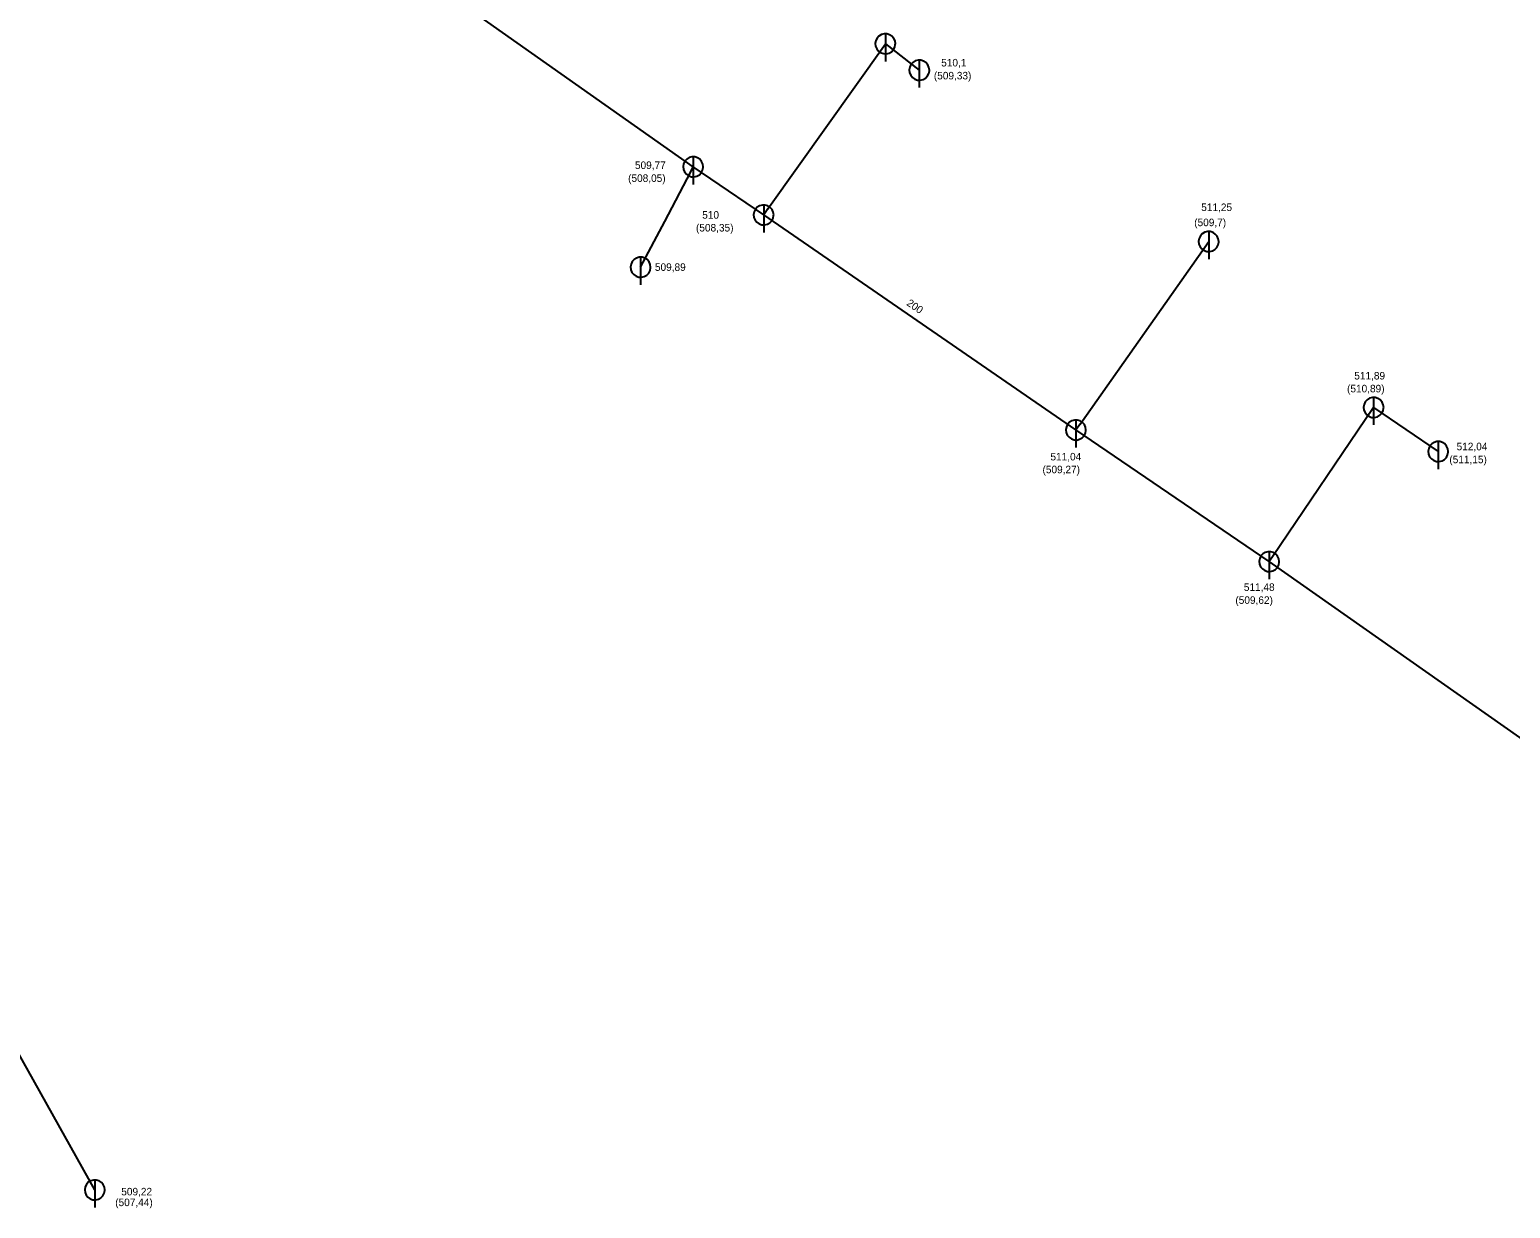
# Model space of a CAD drawing. Extents: x -476058 to -471893, y -1155786 to -1152000.
# Drawn here: x -475206.1 to -475058.6, y -1154421.6 to -1154304.2 of the extents above; entities that cross this region are included whole.
import ezdxf

# ---------------------------------------------------------------- set-up
doc = ezdxf.new("R2010")
doc.units = 0
for name, color, linetype in [('Vrstva 10', 7, 'Continuous'), ('Vrstva 18', 7, 'Continuous'), ('Vrstva 3', 7, 'Continuous'), ('Vrstva 4', 7, 'Continuous'), ('Vrstva 45', 7, 'Continuous'), ('Vrstva 50', 7, 'Continuous'), ('Vrstva 51', 7, 'Continuous')]:
    doc.layers.add(name, color=color, linetype=linetype)

msp = doc.modelspace()

# ---------------------------------------------------------------- linework, layer by layer
at = {"layer": 'Vrstva 10'}
for p, q in [((-475120.87, -1154304.59), (-475120.87, -1154307.34)), ((-475117.49, -1154307.21), (-475117.49, -1154309.96)), ((-475140.01, -1154316.85), (-475140.01, -1154319.6)), ((-475132.99, -1154321.64), (-475132.99, -1154324.39)), ((-475088.67, -1154324.29), (-475088.67, -1154327.04)), ((-475145.25, -1154326.84), (-475145.25, -1154329.59)), ((-475072.24, -1154340.81), (-475072.24, -1154343.56)), ((-475101.89, -1154343.06), (-475101.89, -1154345.81)), ((-475065.81, -1154345.2), (-475065.81, -1154347.95)), ((-475082.64, -1154356.17), (-475082.64, -1154358.92)), ((-475199.61, -1154418.76), (-475199.61, -1154421.51))]:
    msp.add_line(p, q, dxfattribs=at)
for points in [[(-475119.87, -1154305.59), (-475119.91, -1154305.31), (-475120.03, -1154305.05), (-475120.21, -1154304.84), (-475120.45, -1154304.69), (-475120.72, -1154304.6), (-475121, -1154304.6), (-475121.27, -1154304.67), (-475121.51, -1154304.82), (-475121.7, -1154305.03), (-475121.83, -1154305.28), (-475121.87, -1154305.56), (-475121.84, -1154305.84), (-475121.73, -1154306.1), (-475121.55, -1154306.32), (-475121.32, -1154306.48), (-475121.06, -1154306.57), (-475120.77, -1154306.59), (-475120.5, -1154306.52), (-475120.26, -1154306.38), (-475120.06, -1154306.17), (-475119.93, -1154305.92), (-475119.88, -1154305.65), (-475119.87, -1154305.59)], [(-475116.49, -1154308.21), (-475116.53, -1154307.94), (-475116.64, -1154307.68), (-475116.83, -1154307.46), (-475117.06, -1154307.31), (-475117.33, -1154307.23), (-475117.61, -1154307.22), (-475117.89, -1154307.3), (-475118.13, -1154307.45), (-475118.32, -1154307.65), (-475118.44, -1154307.91), (-475118.49, -1154308.19), (-475118.46, -1154308.47), (-475118.35, -1154308.73), (-475118.17, -1154308.95), (-475117.94, -1154309.11), (-475117.67, -1154309.2), (-475117.39, -1154309.21), (-475117.11, -1154309.14), (-475116.87, -1154309), (-475116.67, -1154308.8), (-475116.54, -1154308.55), (-475116.49, -1154308.27), (-475116.49, -1154308.21)], [(-475139.01, -1154317.85), (-475139.05, -1154317.57), (-475139.17, -1154317.31), (-475139.35, -1154317.1), (-475139.59, -1154316.95), (-475139.85, -1154316.86), (-475140.14, -1154316.86), (-475140.41, -1154316.93), (-475140.65, -1154317.08), (-475140.84, -1154317.29), (-475140.96, -1154317.54), (-475141.01, -1154317.82), (-475140.98, -1154318.1), (-475140.87, -1154318.36), (-475140.69, -1154318.58), (-475140.46, -1154318.74), (-475140.19, -1154318.83), (-475139.91, -1154318.85), (-475139.64, -1154318.78), (-475139.39, -1154318.64), (-475139.2, -1154318.43), (-475139.07, -1154318.18), (-475139.01, -1154317.91), (-475139.01, -1154317.85)], [(-475131.99, -1154322.64), (-475132.03, -1154322.36), (-475132.15, -1154322.1), (-475132.33, -1154321.89), (-475132.57, -1154321.74), (-475132.84, -1154321.65), (-475133.12, -1154321.65), (-475133.39, -1154321.72), (-475133.63, -1154321.87), (-475133.82, -1154322.08), (-475133.95, -1154322.33), (-475133.99, -1154322.61), (-475133.96, -1154322.89), (-475133.85, -1154323.15), (-475133.68, -1154323.37), (-475133.45, -1154323.53), (-475133.18, -1154323.62), (-475132.9, -1154323.64), (-475132.62, -1154323.57), (-475132.38, -1154323.43), (-475132.18, -1154323.22), (-475132.05, -1154322.97), (-475132, -1154322.7), (-475131.99, -1154322.64)], [(-475087.67, -1154325.29), (-475087.71, -1154325.01), (-475087.82, -1154324.75), (-475088.01, -1154324.54), (-475088.24, -1154324.39), (-475088.51, -1154324.3), (-475088.79, -1154324.3), (-475089.07, -1154324.37), (-475089.31, -1154324.52), (-475089.5, -1154324.73), (-475089.62, -1154324.98), (-475089.67, -1154325.26), (-475089.64, -1154325.54), (-475089.53, -1154325.8), (-475089.35, -1154326.02), (-475089.12, -1154326.18), (-475088.85, -1154326.27), (-475088.57, -1154326.29), (-475088.29, -1154326.22), (-475088.05, -1154326.08), (-475087.85, -1154325.87), (-475087.73, -1154325.62), (-475087.67, -1154325.35), (-475087.67, -1154325.29)], [(-475144.25, -1154327.84), (-475144.29, -1154327.57), (-475144.41, -1154327.31), (-475144.59, -1154327.09), (-475144.83, -1154326.94), (-475145.1, -1154326.86), (-475145.38, -1154326.85), (-475145.65, -1154326.93), (-475145.89, -1154327.08), (-475146.08, -1154327.28), (-475146.2, -1154327.54), (-475146.25, -1154327.82), (-475146.22, -1154328.1), (-475146.11, -1154328.36), (-475145.93, -1154328.58), (-475145.7, -1154328.74), (-475145.43, -1154328.83), (-475145.15, -1154328.84), (-475144.88, -1154328.77), (-475144.63, -1154328.63), (-475144.44, -1154328.43), (-475144.31, -1154328.18), (-475144.25, -1154327.9), (-475144.25, -1154327.84)], [(-475071.24, -1154341.81), (-475071.28, -1154341.54), (-475071.4, -1154341.28), (-475071.58, -1154341.06), (-475071.82, -1154340.91), (-475072.09, -1154340.83), (-475072.37, -1154340.82), (-475072.64, -1154340.9), (-475072.88, -1154341.05), (-475073.07, -1154341.26), (-475073.2, -1154341.51), (-475073.24, -1154341.79), (-475073.21, -1154342.07), (-475073.1, -1154342.33), (-475072.93, -1154342.55), (-475072.7, -1154342.71), (-475072.43, -1154342.8), (-475072.15, -1154342.81), (-475071.87, -1154342.74), (-475071.63, -1154342.6), (-475071.43, -1154342.4), (-475071.3, -1154342.15), (-475071.25, -1154341.87), (-475071.24, -1154341.81)], [(-475100.89, -1154344.06), (-475100.93, -1154343.78), (-475101.05, -1154343.52), (-475101.23, -1154343.31), (-475101.47, -1154343.16), (-475101.73, -1154343.07), (-475102.02, -1154343.07), (-475102.29, -1154343.14), (-475102.53, -1154343.29), (-475102.72, -1154343.5), (-475102.84, -1154343.75), (-475102.89, -1154344.03), (-475102.86, -1154344.31), (-475102.75, -1154344.57), (-475102.57, -1154344.79), (-475102.34, -1154344.95), (-475102.07, -1154345.04), (-475101.79, -1154345.06), (-475101.52, -1154344.99), (-475101.27, -1154344.85), (-475101.08, -1154344.64), (-475100.95, -1154344.39), (-475100.89, -1154344.12), (-475100.89, -1154344.06)], [(-475064.81, -1154346.2), (-475064.85, -1154345.93), (-475064.97, -1154345.67), (-475065.15, -1154345.45), (-475065.38, -1154345.3), (-475065.65, -1154345.22), (-475065.94, -1154345.21), (-475066.21, -1154345.29), (-475066.45, -1154345.44), (-475066.64, -1154345.64), (-475066.76, -1154345.9), (-475066.81, -1154346.18), (-475066.78, -1154346.46), (-475066.67, -1154346.72), (-475066.49, -1154346.94), (-475066.26, -1154347.1), (-475065.99, -1154347.19), (-475065.71, -1154347.2), (-475065.43, -1154347.13), (-475065.19, -1154346.99), (-475065, -1154346.79), (-475064.87, -1154346.54), (-475064.81, -1154346.26), (-475064.81, -1154346.2)], [(-475081.64, -1154357.17), (-475081.68, -1154356.89), (-475081.8, -1154356.63), (-475081.98, -1154356.42), (-475082.22, -1154356.27), (-475082.48, -1154356.18), (-475082.77, -1154356.18), (-475083.04, -1154356.25), (-475083.28, -1154356.4), (-475083.47, -1154356.61), (-475083.59, -1154356.86), (-475083.64, -1154357.14), (-475083.61, -1154357.42), (-475083.5, -1154357.68), (-475083.32, -1154357.9), (-475083.09, -1154358.06), (-475082.82, -1154358.15), (-475082.54, -1154358.17), (-475082.27, -1154358.1), (-475082.02, -1154357.96), (-475081.83, -1154357.75), (-475081.7, -1154357.5), (-475081.64, -1154357.23), (-475081.64, -1154357.17)], [(-475198.61, -1154419.76), (-475198.65, -1154419.48), (-475198.76, -1154419.22), (-475198.95, -1154419.01), (-475199.18, -1154418.85), (-475199.45, -1154418.77), (-475199.73, -1154418.77), (-475200.01, -1154418.84), (-475200.25, -1154418.99), (-475200.44, -1154419.2), (-475200.56, -1154419.45), (-475200.61, -1154419.73), (-475200.58, -1154420.01), (-475200.47, -1154420.27), (-475200.29, -1154420.49), (-475200.06, -1154420.65), (-475199.79, -1154420.74), (-475199.51, -1154420.75), (-475199.23, -1154420.69), (-475198.99, -1154420.54), (-475198.79, -1154420.34), (-475198.67, -1154420.09), (-475198.61, -1154419.81), (-475198.61, -1154419.76)]]:
    msp.add_lwpolyline(points, dxfattribs=at)
at = {"layer": 'Vrstva 45'}
for points in [[(-475140.01, -1154317.85), (-475163.39, -1154301.39)], [(-475132.99, -1154322.64), (-475140.01, -1154317.85)], [(-475101.89, -1154344.06), (-475132.99, -1154322.64)], [(-475082.64, -1154357.17), (-475101.89, -1154344.06)], [(-475029.59, -1154394.41), (-475082.64, -1154357.17)], [(-475199.61, -1154419.76), (-475232.02, -1154361.76)]]:
    msp.add_lwpolyline(points, dxfattribs=at)
at = {"layer": 'Vrstva 50'}
for p, q in [((-475132.57, -1154322.04), (-475120.87, -1154305.59)), ((-475120.87, -1154305.59), (-475117.49, -1154308.21)), ((-475140.26, -1154318.33), (-475140.01, -1154317.85)), ((-475101.48, -1154343.47), (-475088.67, -1154325.29))]:
    msp.add_line(p, q, dxfattribs=at)
for points in [[(-475145.25, -1154327.84), (-475142.84, -1154323.3), (-475140.26, -1154318.33)], [(-475132.57, -1154322.04), (-475132.99, -1154322.64)], [(-475072.24, -1154341.81), (-475082.32, -1154356.7), (-475082.64, -1154357.17)], [(-475101.48, -1154343.47), (-475101.89, -1154344.06)]]:
    msp.add_lwpolyline(points, dxfattribs=at)
at = {"layer": 'Vrstva 51'}
msp.add_line((-475072.24, -1154341.81), (-475065.81, -1154346.2), dxfattribs=at)

# ---------------------------------------------------------------- texts
at = {"layer": 'Vrstva 18'}
msp.add_text('200 ', height=0.75, rotation=325.4883, dxfattribs=at).set_placement((-475118.82, -1154331.58))
at = {"layer": 'Vrstva 3'}
for s, p in [('510,1', (-475115.31, -1154307.85)), ('509,77', (-475145.81, -1154318.06)), ('510', (-475139.11, -1154323.01)), ('511,25', (-475089.41, -1154322.25)), ('509,89 ', (-475143.82, -1154328.21)), ('511,89', (-475074.17, -1154339.03)), ('511,04', (-475104.43, -1154347.09)), ('512,04', (-475063.98, -1154346.08)), ('511,48', (-475085.17, -1154360.09)), ('509,22', (-475196.97, -1154420.3))]:
    msp.add_text(s, height=0.75, dxfattribs=at).set_placement(p)
at = {"layer": 'Vrstva 4'}
for s, p in [('(509,33)', (-475116.04, -1154309.14)), ('(508,05)', (-475146.49, -1154319.35)), ('(508,35)', (-475139.73, -1154324.29)), ('(509,7)', (-475090.11, -1154323.76)), ('(510,89)', (-475074.89, -1154340.31)), ('(509,27)', (-475105.22, -1154348.37)), ('(511,15)', (-475064.7, -1154347.37)), ('(509,62)', (-475086.01, -1154361.38)), ('(507,44)', (-475197.57, -1154421.37))]:
    msp.add_text(s, height=0.75, dxfattribs=at).set_placement(p)

doc.saveas('drawing.dxf')
